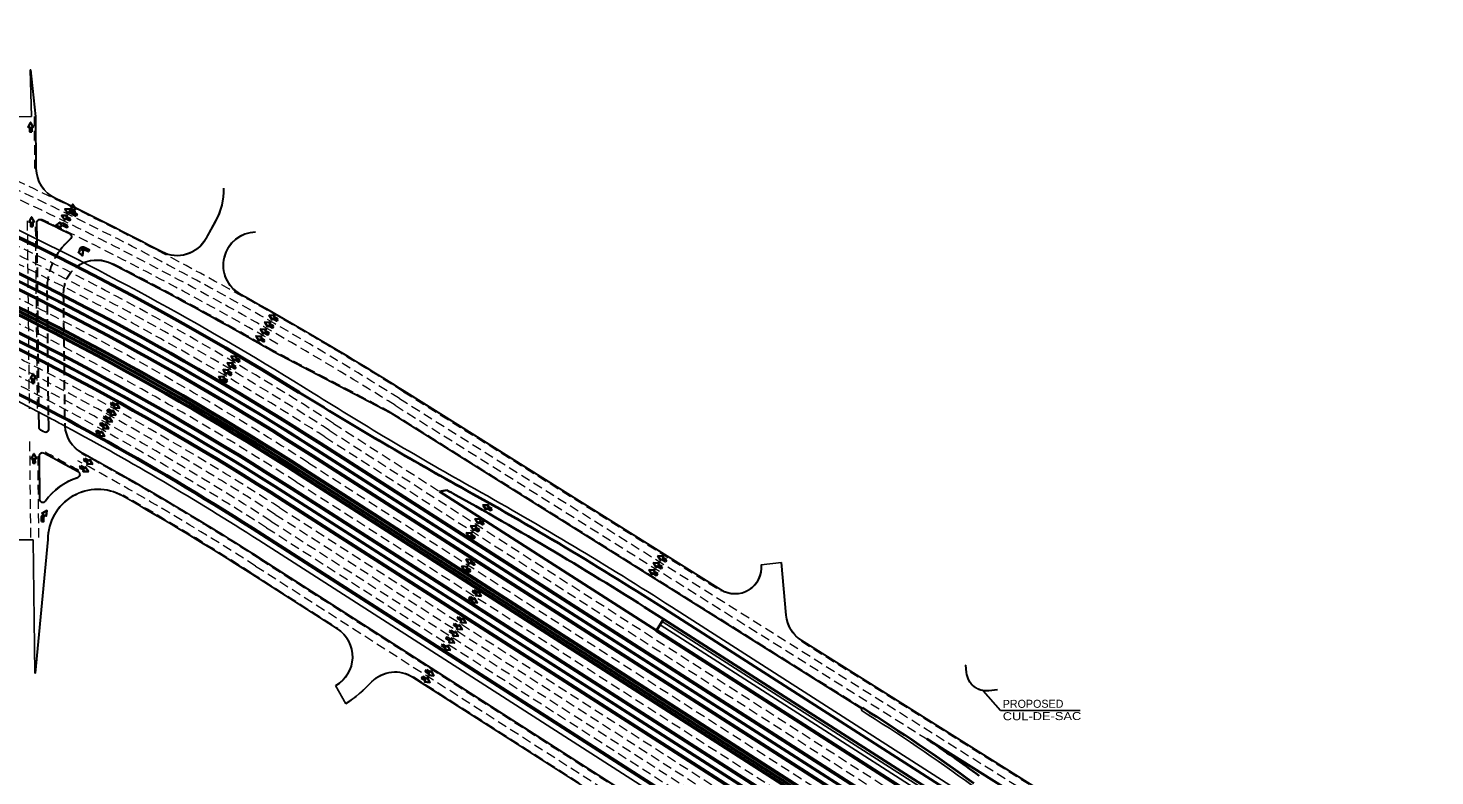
# Model space of a CAD drawing. Extents: x 2326434 to 2368642, y 6985225 to 6995090.
# Drawn here: x 2359477 to 2361586, y 6990546 to 6991668 of the extents above; entities that cross this region are included whole.
import ezdxf

# ---------------------------------------------------------------- set-up
doc = ezdxf.new("R2010")
doc.units = 0
doc.header["$LTSCALE"] = 4.8
doc.linetypes.add('MEDIUM_DASHED', pattern=[4.5, 3, -1.5])
for name, color, linetype, lineweight in [('10', 7, 'Continuous', 35), ('26', 7, 'Continuous', 25), ('27', 7, 'Continuous', 25), ('28', 7, 'Continuous', 25), ('30', 7, 'Continuous', 25), ('40', 7, 'Continuous', 35), ('50', 7, 'MEDIUM_DASHED', 13), ('61', 7, 'Continuous', 35)]:
    doc.layers.add(name, color=color, linetype=linetype, lineweight=lineweight)

msp = doc.modelspace()

# ---------------------------------------------------------------- linework, layer by layer
at = {"layer": '10'}
for p, q in [((2360093.62, 6990973.081), (2360104.786, 6990974.855)), ((2360093.62, 6990973.081), (2360419.022, 6990764.424)), ((2360419.022, 6990764.424), (2360429.817, 6990781.26)), ((2360824.533, 6990601.69), (2361047.306, 6990461.866))]:
    msp.add_line(p, q, dxfattribs=at)
for centre, radius, start, end in [((2362905.331, 6995989.398), 5743.578, 240.81732, 240.97026), ((2357344.619, 6985969.879), 5715.578, 57.33082, 60.97026), ((2359212.479, 6988233.533), 2864.789, 53.83091, 55.74425)]:
    msp.add_arc(centre, radius, start, end, dxfattribs=at)
at = {"layer": '26'}
for p, q in [((2359909.905, 6991036.24), (2361568.078, 6989972.971)), ((2359865.643, 6990967.212), (2361511.986, 6989911.529)), ((2359822.46, 6990899.868), (2360800.761, 6990272.552)), ((2360424.42, 6990772.842), (2361439.725, 6990121.799))]:
    msp.add_line(p, q, dxfattribs=at)
at = {"layer": '26', "lineweight": 53}
for p, q in [((2359915.303, 6991044.658), (2361573.475, 6989981.389)), ((2359860.245, 6990958.794), (2361506.588, 6989903.111)), ((2359827.857, 6990908.286), (2360783.423, 6990295.549)), ((2360419.022, 6990764.424), (2361434.327, 6990113.381))]:
    msp.add_line(p, q, dxfattribs=at)
for radius, start, end in [(4644.17, 57.33083, 76.17156), (4692.17, 58.16706, 70.78826), (4542.17, 57.33083, 76.64157), (4482.17, 57.33083, 71.13542)]:
    msp.add_arc((2357408.438, 6987135.189), radius, start, end, dxfattribs=at)
at = {"layer": '26'}
for radius, start, end in [(4634.17, 57.33083, 76.17156), (4702.17, 57.9444, 71.09845), (4552.17, 57.33083, 76.64157), (4472.17, 62.09493, 71.52898), (4472.17, 61.93706, 62.09493), (4472.17, 61.67834, 61.93706), (4472.17, 61.62442, 61.67834), (4472.17, 57.33083, 61.62442)]:
    msp.add_arc((2357408.438, 6987135.189), radius, start, end, dxfattribs=at)
at = {"layer": '27'}
for p, q in [((2360441.693, 6990799.78), (2360873.186, 6990523.093)), ((2360427.658, 6990777.893), (2360859.152, 6990501.207)), ((2360728.002, 6990648.111), (2360725.876, 6990644.723))]:
    msp.add_line(p, q, dxfattribs=at)
at = {"layer": '27', "lineweight": 40}
for p, q in [((2360429.817, 6990781.26), (2360861.311, 6990504.574)), ((2360868.868, 6990516.359), (2360437.374, 6990793.045))]:
    msp.add_line(p, q, dxfattribs=at)
for centre, radius, start, end in [((2362905.331, 6995989.398), 5729.578, 238.16706, 240.97026), ((2357344.619, 6985969.879), 5729.578, 57.33082, 60.97026), ((2359212.479, 6988233.533), 2850.789, 53.83091, 57.88533)]:
    msp.add_arc(centre, radius, start, end, dxfattribs=at)
at = {"layer": '27'}
for centre, radius, start, end in [((2362945.005, 6995976.445), 5729.578, 237.9444, 240.76552), ((2357344.619, 6985969.879), 5737.578, 57.33082, 60.76552), ((2359212.479, 6988233.533), 2846.789, 53.83091, 57.88532)]:
    msp.add_arc(centre, radius, start, end, dxfattribs=at)
at = {"layer": '28'}
for p, q in [((2359480.856, 6991605.434), (2359479.78, 6991605.423)), ((2359481.804, 6991535.44), (2359479.78, 6991605.423)), ((2359480.354, 6991605.429), (2359487.622, 6991535.502)), ((2359480.856, 6991605.434), (2359488.119, 6991535.554)), ((2359481.804, 6991535.44), (2359440.498, 6991535.001)), ((2359487.622, 6991535.502), (2359488.451, 6991457.513)), ((2359488.122, 6991535.508), (2359488.951, 6991457.519)), ((2359489.317, 6991376.025), (2359489.57, 6991352.213)), ((2359489.817, 6991376.03), (2359490.073, 6991351.949)), ((2359743.521, 6991352.864), (2359757.7, 6991378.749)), ((2359743.959, 6991352.623), (2359758.138, 6991378.509)), ((2360020.595, 6991090.348), (2359844.502, 6991182.42)), ((2360020.86, 6991090.772), (2359844.752, 6991182.853)), ((2360040.378, 6991123.386), (2360515.449, 6990825.206)), ((2360040.644, 6991123.81), (2360515.715, 6990825.629)), ((2359492.337, 6991091.889), (2359492.577, 6991069.333)), ((2359492.839, 6991091.751), (2359493.077, 6991069.338)), ((2359506.917, 6991084.449), (2359507.033, 6991073.523)), ((2359507.42, 6991084.182), (2359507.533, 6991073.528)), ((2360020.595, 6991090.348), (2360727.205, 6990646.84)), ((2360020.86, 6991090.772), (2360727.471, 6990647.264)), ((2359493.036, 6991026.108), (2359493.726, 6990961.182)), ((2359493.536, 6991026.113), (2359494.226, 6990961.187)), ((2359484.355, 6990900.416), (2359455.751, 6990900.112)), ((2359486.967, 6990700.432), (2359484.355, 6990900.416)), ((2359487.267, 6990700.435), (2359506.371, 6990900.65)), ((2359487.77, 6990700.441), (2359506.868, 6990900.602)), ((2359824.932, 6990872.004), (2360583.409, 6990385.96)), ((2359825.202, 6990872.425), (2360583.678, 6990386.381)), ((2360576.01, 6990863.087), (2360606.706, 6990866.213)), ((2360606.209, 6990866.162), (2360613.192, 6990787.223)), ((2360606.706, 6990866.213), (2360613.69, 6990787.267)), ((2359810.634, 6990849.692), (2359940.019, 6990766.78)), ((2359810.904, 6990850.113), (2359940.512, 6990767.058)), ((2360636.416, 6990749.279), (2361262.16, 6990356.528)), ((2360636.682, 6990749.703), (2361262.425, 6990356.952)), ((2359487.77, 6990700.441), (2359486.967, 6990700.432)), ((2360053.855, 6990693.832), (2360353.858, 6990501.586)), ((2360054.125, 6990694.253), (2360354.127, 6990502.007)), ((2360882.984, 6990712.377), (2360882.486, 6990712.327)), ((2360882.486, 6990712.327), (2360883.61, 6990701.072)), ((2360882.984, 6990712.377), (2360884.107, 6990701.122)), ((2359937.844, 6990681.84), (2359953.365, 6990654.31)), ((2360930.382, 6990675.749), (2360917.289, 6990674.286)), ((2360930.438, 6990675.252), (2360917.345, 6990673.789))]:
    msp.add_line(p, q, dxfattribs=at)
at = {"layer": '28', "linetype": 'MEDIUM_DASHED'}
for p, q in [((2359489.57, 6991352.213), (2359492.337, 6991091.89)), ((2359490.073, 6991351.949), (2359492.839, 6991091.751)), ((2359504.897, 6991274.457), (2359506.917, 6991084.449)), ((2359505.397, 6991274.463), (2359507.42, 6991084.182)), ((2359529.45, 6991269.667), (2359531.532, 6991073.784)), ((2359529.95, 6991269.672), (2359532.032, 6991073.789))]:
    msp.add_line(p, q, dxfattribs=at)
at = {"layer": '28'}
for centre, radius, start, end in [((2359538.448, 6991458.045), 50, 180.60899, 244.22244), ((2359538.448, 6991458.045), 49.5, 180.60899, 244.22244), ((2357162.546, 6986538.339), 5413.37, 62.3242, 64.22244), ((2357162.546, 6986538.339), 5413.87, 62.3242, 64.22244), ((2359670.434, 6991426.55), 99.5, 331.28739, 0.77367), ((2359670.434, 6991426.55), 100, 331.28739, 0.77367), ((2359494.317, 6991376.078), 5, 64.26613, 180.60899), ((2359494.317, 6991376.078), 4.5, 64.26613, 180.60899), ((2357162.546, 6986538.339), 5374.87, 63.75886, 64.26613), ((2357162.546, 6986538.339), 5375.37, 63.75886, 64.26613), ((2359605.392, 6991275.525), 100.5, 130.60347, 143.90422), ((2359605.392, 6991275.525), 100, 130.60347, 143.75392), ((2359537.056, 6991355.245), 4.5, 310.60347, 63.75886), ((2359537.056, 6991355.245), 5, 310.60347, 63.75886), ((2359700.107, 6991376.644), 50, 242.3242, 331.28739), ((2359700.107, 6991376.644), 49.5, 242.3242, 331.28739), ((2359819.118, 6991312.335), 50, 91.54724, 240.90551), ((2359819.118, 6991312.335), 49.5, 91.54724, 240.90551), ((2359579.447, 6991270.198), 50, 62.94334, 112.91716), ((2359579.447, 6991270.198), 49.5, 62.94334, 112.43241), ((2357162.546, 6986538.339), 5362.87, 59.99357, 62.94334), ((2357162.546, 6986538.339), 5363.37, 59.99357, 62.94334), ((2357162.546, 6986538.339), 5413.37, 57.88533, 60.90551), ((2357162.546, 6986538.339), 5413.87, 57.88533, 60.90551), ((2359581.529, 6991074.315), 74.5, 180.60898, 185.62), ((2359581.529, 6991074.315), 74, 180.60898, 185.62), ((2359497.577, 6991069.386), 5, 180.60899, 242.27292), ((2359497.577, 6991069.386), 4.5, 180.60899, 242.27292), ((2357426.888, 6987129.831), 4445.6, 62.19535, 62.27292), ((2357426.888, 6987129.831), 4446.1, 62.19535, 62.27292), ((2359502.909, 6991066.578), 5, 242.19535, 5.62001), ((2359502.909, 6991066.578), 4.5, 242.19535, 5.62001), ((2359581.529, 6991074.315), 50, 183.54262, 241.35481), ((2359581.529, 6991074.315), 49.5, 183.90344, 241.35481), ((2359498.036, 6991026.161), 5, 62.00651, 180.60899), ((2357426.888, 6987129.831), 4445.1, 57.34761, 61.35481), ((2359498.036, 6991026.161), 4.5, 62.00651, 180.60899), ((2357426.888, 6987129.831), 4417.1, 61.24662, 62.00651), ((2357426.888, 6987129.831), 4417.6, 61.24662, 62.00651), ((2357426.888, 6987129.831), 4444.6, 57.34786, 61.35481), ((2359581.366, 6990901.447), 97.5, 108.18854, 144.11522), ((2359581.366, 6990901.447), 97, 108.18854, 144.11522), ((2359549.527, 6990998.35), 4.5, 288.18854, 61.24662), ((2359549.527, 6990998.35), 5, 288.18854, 61.24662), ((2359581.366, 6990901.447), 75, 60.26349, 180.60898), ((2359581.366, 6990901.447), 74.5, 60.26349, 180.60898), ((2359498.726, 6990961.235), 5, 180.60899, 324.11522), ((2359498.726, 6990961.235), 4.5, 180.60899, 324.11522), ((2357426.888, 6987129.831), 4418.1, 57.34761, 60.26349), ((2357426.888, 6987129.831), 4418.6, 57.34761, 60.26349), ((2360536.713, 6990859.085), 40, 237.88532, 5.81505), ((2360536.713, 6990859.085), 39.5, 237.88532, 5.81505), ((2360662.997, 6990791.629), 50, 185.05534, 237.88532), ((2360662.997, 6990791.629), 49.5, 185.05534, 237.88532), ((2359913.535, 6990724.96), 49.5, 299.41298, 57.34761), ((2359913.535, 6990724.96), 50, 299.41298, 57.34761), ((2360027.148, 6990652.155), 50, 57.34761, 134.99556), ((2360027.148, 6990652.155), 49.5, 57.34761, 134.99556), ((2360913.959, 6990704.101), 30.5, 185.69903, 276.37395), ((2360913.959, 6990704.101), 30, 185.69903, 276.37395), ((2359834.963, 6990833.422), 214.21, 303.46682, 317.06169), ((2359834.963, 6990833.422), 214.71, 303.46682, 317.06169)]:
    msp.add_arc(centre, radius, start, end, dxfattribs=at)
at = {"layer": '28', "linetype": 'MEDIUM_DASHED'}
for centre, radius, start, end in [((2359605.392, 6991275.525), 100.5, 143.90447, 180.60898), ((2359605.392, 6991275.525), 100, 143.75393, 180.60898), ((2359579.447, 6991270.198), 50, 112.91716, 180.60899), ((2359579.447, 6991270.198), 49.5, 112.43241, 180.60899), ((2359581.529, 6991074.315), 50, 180.60899, 183.54262), ((2359581.529, 6991074.315), 49.5, 180.60899, 183.90345)]:
    msp.add_arc(centre, radius, start, end, dxfattribs=at)
at = {"layer": '30'}
for p, q in [((2359908.826, 6991034.556), (2361566.998, 6989971.288)), ((2359908.826, 6991034.556), (2361430.275, 6990058.958)), ((2359887.234, 6991000.884), (2361545.407, 6989937.615)), ((2359887.234, 6991000.884), (2361408.684, 6990025.286)), ((2359888.314, 6991002.568), (2361546.486, 6989939.299)), ((2359888.314, 6991002.568), (2361409.763, 6990026.97)), ((2359866.722, 6990968.896), (2361524.895, 6989905.627))]:
    msp.add_line(p, q, dxfattribs=at)
at = {"layer": '30', "lineweight": 53}
for p, q in [((2359903.428, 6991026.138), (2361561.6, 6989962.87)), ((2359903.428, 6991026.138), (2361424.877, 6990050.54)), ((2359885.075, 6990997.517), (2361543.247, 6989934.248)), ((2359885.075, 6990997.517), (2361406.525, 6990021.919)), ((2359890.473, 6991005.935), (2361548.645, 6989942.666)), ((2359890.473, 6991005.935), (2361411.922, 6990030.337)), ((2359872.12, 6990977.314), (2361530.292, 6989914.045)), ((2359872.12, 6990977.314), (2361393.57, 6990001.716))]:
    msp.add_line(p, q, dxfattribs=at)
for radius in [4622.17, 4588.17, 4598.17, 4564.17]:
    msp.add_arc((2357408.438, 6987135.189), radius, 57.33083, 76.17156, dxfattribs=at)
at = {"layer": '30'}
for radius in [4632.17, 4592.17, 4594.17, 4554.17]:
    msp.add_arc((2357408.438, 6987135.189), radius, 57.33083, 76.17156, dxfattribs=at)
at = {"layer": '40'}
for points in [[(2359482.207, 6991512.709), (2359479.207, 6991512.689), (2359479.162, 6991519.496), (2359476.725, 6991519.48), (2359480.456, 6991526.704), (2359484.282, 6991519.529), (2359482.163, 6991519.515)], [(2359543.565, 6991388.946), (2359544.901, 6991391.634), (2359538.805, 6991394.663), (2359539.89, 6991396.846), (2359531.76, 6991396.666), (2359536.526, 6991390.078), (2359537.47, 6991391.976)], [(2359548.873, 6991386.183), (2359543.565, 6991388.946), (2359543.107, 6991396.37), (2359540.687, 6991396.076), (2359543.573, 6991403.679), (2359548.19, 6991396.986), (2359546.086, 6991396.731), (2359546.503, 6991390.763), (2359550.238, 6991388.887)], [(2359483.651, 6991370.491), (2359480.651, 6991370.471), (2359480.606, 6991377.277), (2359478.169, 6991377.261), (2359481.9, 6991384.486), (2359485.726, 6991377.311), (2359483.607, 6991377.297)], [(2359536.32, 6991371.671), (2359529.221, 6991375.237), (2359524.926, 6991374.352), (2359524.529, 6991376.757), (2359518.04, 6991371.857), (2359525.759, 6991369.3), (2359525.414, 6991371.391), (2359528.802, 6991372.09), (2359534.973, 6991368.99)], [(2359540.278, 6991382.138), (2359538.946, 6991379.449), (2359532.847, 6991382.47), (2359531.765, 6991380.286), (2359526.99, 6991386.868), (2359535.119, 6991387.058), (2359534.178, 6991385.159)], [(2359844.584, 6991220.921), (2359842.989, 6991218.379), (2359837.223, 6991221.997), (2359835.928, 6991219.932), (2359831.837, 6991226.96), (2359839.944, 6991226.334), (2359838.818, 6991224.539)], [(2359851.156, 6991231.334), (2359849.561, 6991228.793), (2359843.795, 6991232.41), (2359842.5, 6991230.345), (2359838.409, 6991237.373), (2359846.517, 6991236.747), (2359845.39, 6991234.952)], [(2359831.439, 6991200.095), (2359829.844, 6991197.553), (2359824.079, 6991201.171), (2359822.783, 6991199.106), (2359818.693, 6991206.134), (2359826.8, 6991205.508), (2359825.673, 6991203.712)], [(2359838.012, 6991210.508), (2359836.417, 6991207.966), (2359830.651, 6991211.584), (2359829.356, 6991209.519), (2359825.265, 6991216.547), (2359833.372, 6991215.921), (2359832.246, 6991214.126)], [(2359788.451, 6991159.756), (2359786.857, 6991157.214), (2359781.091, 6991160.832), (2359779.795, 6991158.767), (2359775.705, 6991165.795), (2359783.812, 6991165.169), (2359782.686, 6991163.374)], [(2359794.059, 6991169.872), (2359792.465, 6991167.33), (2359786.699, 6991170.948), (2359785.403, 6991168.883), (2359781.313, 6991175.911), (2359789.42, 6991175.285), (2359788.294, 6991173.49)], [(2359485.829, 6991135.602), (2359482.828, 6991135.582), (2359482.783, 6991142.388), (2359480.346, 6991142.372), (2359484.077, 6991149.597), (2359487.903, 6991142.422), (2359485.784, 6991142.408)], [(2359775.474, 6991139.245), (2359773.879, 6991136.703), (2359768.113, 6991140.321), (2359766.818, 6991138.256), (2359762.727, 6991145.284), (2359770.835, 6991144.658), (2359769.708, 6991142.863)], [(2359782.046, 6991149.658), (2359780.451, 6991147.117), (2359774.686, 6991150.734), (2359773.39, 6991148.669), (2359769.299, 6991155.697), (2359777.407, 6991155.071), (2359776.28, 6991153.276)], [(2359596.982, 6991096.14), (2359595.445, 6991093.563), (2359601.29, 6991090.075), (2359600.041, 6991087.982), (2359608.16, 6991087.538), (2359603.913, 6991094.472), (2359602.827, 6991092.652)], [(2359602.413, 6991106.322), (2359600.875, 6991103.745), (2359606.721, 6991100.257), (2359605.472, 6991098.164), (2359613.591, 6991097.72), (2359609.344, 6991104.654), (2359608.258, 6991102.834)], [(2359586.12, 6991075.775), (2359584.583, 6991073.198), (2359590.428, 6991069.71), (2359589.179, 6991067.617), (2359597.298, 6991067.173), (2359593.052, 6991074.107), (2359591.965, 6991072.287)], [(2359591.551, 6991085.957), (2359590.014, 6991083.381), (2359595.859, 6991079.893), (2359594.61, 6991077.8), (2359602.729, 6991077.355), (2359598.482, 6991084.29), (2359597.396, 6991082.47)], [(2359580.282, 6991064.617), (2359578.745, 6991062.04), (2359584.59, 6991058.552), (2359583.341, 6991056.459), (2359591.46, 6991056.014), (2359587.214, 6991062.949), (2359586.128, 6991061.129)], [(2359487.05, 6991015.588), (2359484.049, 6991015.569), (2359484.005, 6991022.375), (2359481.567, 6991022.359), (2359485.299, 6991029.584), (2359489.125, 6991022.409), (2359487.005, 6991022.395)], [(2359555.997, 6991011.221), (2359554.46, 6991008.644), (2359560.305, 6991005.156), (2359559.056, 6991003.063), (2359567.175, 6991002.619), (2359562.929, 6991009.553), (2359561.843, 6991007.733)], [(2359561.835, 6991022.38), (2359560.298, 6991019.803), (2359566.143, 6991016.315), (2359564.894, 6991014.222), (2359573.013, 6991013.778), (2359568.766, 6991020.712), (2359567.68, 6991018.892)], [(2360171.957, 6990947.029), (2360170.468, 6990944.424), (2360164.558, 6990947.802), (2360163.349, 6990945.686), (2360158.973, 6990952.54), (2360167.1, 6990952.247), (2360166.048, 6990950.407)], [(2359496.959, 6990927.652), (2359496.92, 6990935.596), (2359499.622, 6990939.051), (2359497.644, 6990940.475), (2359504.917, 6990944.11), (2359503.777, 6990936.059), (2359502.057, 6990937.297), (2359499.926, 6990934.572), (2359499.96, 6990927.667)], [(2360160.046, 6990925.827), (2360158.451, 6990923.286), (2360152.685, 6990926.903), (2360151.39, 6990924.839), (2360147.299, 6990931.866), (2360155.407, 6990931.24), (2360154.28, 6990929.445)], [(2360146.901, 6990905.001), (2360145.307, 6990902.459), (2360139.541, 6990906.077), (2360138.245, 6990904.012), (2360134.155, 6990911.04), (2360142.262, 6990910.414), (2360141.136, 6990908.619)], [(2360153.474, 6990915.414), (2360151.879, 6990912.872), (2360146.113, 6990916.49), (2360144.818, 6990914.425), (2360140.727, 6990921.453), (2360148.834, 6990920.827), (2360147.708, 6990919.032)], [(2360146.608, 6990865.067), (2360145.013, 6990862.526), (2360139.247, 6990866.143), (2360137.952, 6990864.079), (2360133.861, 6990871.106), (2360141.968, 6990870.48), (2360140.842, 6990868.685)], [(2360427.442, 6990859.848), (2360425.848, 6990857.306), (2360420.082, 6990860.924), (2360418.786, 6990858.859), (2360414.696, 6990865.887), (2360422.803, 6990865.261), (2360421.677, 6990863.466)], [(2360434.015, 6990870.261), (2360432.42, 6990867.719), (2360426.654, 6990871.337), (2360425.359, 6990869.272), (2360421.268, 6990876.3), (2360429.375, 6990875.674), (2360428.249, 6990873.879)], [(2360140.035, 6990854.654), (2360138.441, 6990852.112), (2360132.675, 6990855.73), (2360131.38, 6990853.665), (2360127.289, 6990860.693), (2360135.396, 6990860.067), (2360134.27, 6990858.272)], [(2360420.87, 6990849.435), (2360419.275, 6990846.893), (2360413.509, 6990850.51), (2360412.214, 6990848.446), (2360408.123, 6990855.474), (2360416.231, 6990854.848), (2360415.104, 6990853.052)], [(2360145.263, 6990824.975), (2360143.637, 6990822.453), (2360149.358, 6990818.764), (2360148.038, 6990816.716), (2360156.137, 6990815.991), (2360152.133, 6990823.068), (2360150.984, 6990821.287)], [(2360139.483, 6990814.986), (2360137.857, 6990812.464), (2360143.578, 6990808.776), (2360142.258, 6990806.728), (2360150.357, 6990806.002), (2360146.353, 6990813.08), (2360145.204, 6990811.298)], [(2360122.327, 6990784.72), (2360120.701, 6990782.198), (2360126.422, 6990778.51), (2360125.102, 6990776.461), (2360133.201, 6990775.736), (2360129.197, 6990782.813), (2360128.048, 6990781.032)], [(2360110.767, 6990764.743), (2360109.141, 6990762.221), (2360114.862, 6990758.533), (2360113.542, 6990756.484), (2360121.641, 6990755.759), (2360117.637, 6990762.837), (2360116.488, 6990761.055)], [(2360116.547, 6990774.732), (2360114.921, 6990772.209), (2360120.642, 6990768.521), (2360119.322, 6990766.473), (2360127.421, 6990765.748), (2360123.417, 6990772.825), (2360122.268, 6990771.043)], [(2360098.657, 6990743.705), (2360097.031, 6990741.183), (2360102.752, 6990737.495), (2360101.432, 6990735.446), (2360109.531, 6990734.721), (2360105.527, 6990741.798), (2360104.378, 6990740.017)], [(2360104.987, 6990754.755), (2360103.361, 6990752.233), (2360109.082, 6990748.545), (2360107.762, 6990746.496), (2360115.861, 6990745.771), (2360111.857, 6990752.848), (2360110.708, 6990751.067)], [(2360068.474, 6990695.528), (2360066.848, 6990693.006), (2360072.569, 6990689.318), (2360071.249, 6990687.269), (2360079.348, 6990686.544), (2360075.343, 6990693.621), (2360074.195, 6990691.84)], [(2360074.254, 6990705.516), (2360072.628, 6990702.994), (2360078.349, 6990699.306), (2360077.029, 6990697.257), (2360085.128, 6990696.532), (2360081.123, 6990703.609), (2360079.975, 6990701.828)]]:
    msp.add_lwpolyline(points, close=True, dxfattribs=at)
for points in [[(2359557.09, 6991333.802), (2359559.036, 6991334.619), (2359558.339, 6991326.518), (2359552.068, 6991331.694), (2359554.315, 6991332.637)], [(2359561.287, 6991339.057), (2359568.445, 6991335.612), (2359567.144, 6991332.908), (2359559.791, 6991336.447), (2359559.835, 6991336.423)]]:
    msp.add_lwpolyline(points, dxfattribs=at)
for radius, start, end in [(4.997, 61.13978, 204.14461), (1.989, 61.13979, 206.21843)]:
    msp.add_arc((2359558.875, 6991334.681), radius, start, end, dxfattribs=at)
at = {"layer": '50'}
for p, q in [((2359485.622, 6991535.481), (2359486.45, 6991457.53)), ((2359475.284, 6991378.974), (2359478.283, 6991096.854)), ((2359487.381, 6991369.967), (2359490.28, 6991097.286)), ((2360021.392, 6991091.619), (2359845.253, 6991183.719)), ((2360039.846, 6991122.539), (2360515.895, 6990823.745)), ((2360027.088, 6991102.212), (2360824.533, 6990601.69)), ((2360033.467, 6991112.376), (2361255.249, 6990345.517)), ((2359934.735, 6991074.963), (2360093.62, 6990973.081)), ((2360021.392, 6991091.619), (2360728.002, 6990648.111)), ((2359921.781, 6991054.759), (2361579.953, 6989991.491)), ((2359928.258, 6991064.861), (2361586.43, 6990001.592)), ((2359478.805, 6991047.726), (2359480.371, 6990900.373)), ((2359491.036, 6991026.086), (2359492.371, 6990900.501)), ((2359896.95, 6991016.037), (2361555.123, 6989952.768)), ((2359896.95, 6991016.037), (2361418.4, 6990040.439)), ((2359878.598, 6990987.415), (2361536.77, 6989924.147)), ((2359878.598, 6990987.415), (2361400.047, 6990011.817)), ((2359853.767, 6990948.692), (2361500.11, 6989893.009)), ((2359840.812, 6990928.489), (2360796.378, 6990315.753)), ((2359847.29, 6990938.591), (2361500.789, 6989878.319)), ((2359834.335, 6990918.388), (2360789.9, 6990305.651)), ((2359824.392, 6990871.162), (2360582.869, 6990385.118)), ((2359811.443, 6990850.955), (2359941.051, 6990767.9)), ((2359817.918, 6990861.058), (2360576.394, 6990375.014)), ((2360636.34, 6990748.147), (2361261.628, 6990355.681)), ((2360054.665, 6990695.095), (2360354.667, 6990502.849))]:
    msp.add_line(p, q, dxfattribs=at)
for centre, radius, start, end in [((2357408.438, 6987135.189), 4668.17, 57.33083, 76.17156), ((2357408.438, 6987135.189), 4656.17, 57.33083, 76.17156), ((2357408.438, 6987135.189), 4610.17, 57.33083, 76.17156), ((2357408.438, 6987135.189), 4576.17, 57.33083, 76.17156), ((2357408.438, 6987135.189), 4530.17, 57.33083, 76.64157), ((2357408.438, 6987135.189), 4680.17, 57.33083, 70.83494), ((2357408.438, 6987135.189), 4506.17, 57.33083, 76.64157), ((2357408.438, 6987135.189), 4518.17, 57.33083, 76.64157), ((2357408.438, 6987135.189), 4494.17, 57.33083, 75.30877), ((2357162.546, 6986538.339), 5400.37, 57.88533, 66.12964), ((2357162.546, 6986538.339), 5412.37, 57.88533, 66.12964), ((2357162.546, 6986538.339), 5388.37, 57.88533, 66.12964), ((2357162.546, 6986538.339), 5376.37, 59.99357, 64.26613), ((2357162.546, 6986538.339), 5364.37, 59.99357, 62.94334), ((2357426.888, 6987129.831), 4419.6, 61.24662, 62.00651), ((2357426.888, 6987129.831), 4431.6, 57.34761, 61.35481), ((2357426.888, 6987129.831), 4443.6, 57.34761, 61.35481), ((2357426.888, 6987129.831), 4419.6, 57.34761, 60.26349)]:
    msp.add_arc(centre, radius, start, end, dxfattribs=at)
at = {"layer": '61', "lineweight": 25}
msp.add_lwpolyline([(2360908.797, 6990674.041), (2360935.063, 6990644.368), (2361054.631, 6990644.368)], dxfattribs=at)

# ---------------------------------------------------------------- texts
at = {"layer": '61'}
msp.add_text('PROPOSED', height=12, rotation=0.15, dxfattribs=at).set_placement((2360938.393, 6990648.259))
at = {"layer": '61', "width": 1.2}
msp.add_text('CUL-DE-SAC', height=12, rotation=0.15, dxfattribs=at).set_placement((2360938.441, 6990629.697))

doc.saveas('drawing.dxf')
